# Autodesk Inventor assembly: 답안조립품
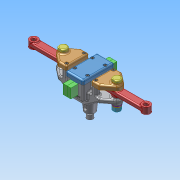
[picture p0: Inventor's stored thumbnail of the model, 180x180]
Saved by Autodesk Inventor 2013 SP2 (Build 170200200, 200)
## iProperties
Created: 2025-07
Part Number: 답안조립품
Document SubType Name: Assembly
Designer: a
Author: a
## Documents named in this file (11)
- C:\Users\a\Desktop\750703V1007\답안조립품.iam
- C:\Users\a\Desktop\750703V1007\본체.ipt
- C:\Users\a\Desktop\750703V1007\링크.ipt
- C:\Users\a\Desktop\750703V1007\슬라이더.ipt
- C:\Users\a\Desktop\750703V1007\링크 커버.ipt
- C:\Users\a\Desktop\750703V1007\슬라이더 커버.ipt
- C:\Users\a\Desktop\750703V1007\평 와셔 M8.ipt
- C:\Users\a\Desktop\750703V1007\스프링 와셔 M8.ipt
- C:\Users\a\Desktop\750703V1007\6각 너트 M8.ipt
- C:\Users\a\Desktop\750703V1007\핀.ipt
- C:\Users\a\Desktop\750703V1007\6각 구멍붙이 볼트 M3x10.ipt
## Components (12 placed, 3 different names)
1. 6각 너트 M8:1 — 각도:5
2. 핀:1 — 각도:4
3. 핀:2 — 각도:2
4. 6각 너트 M8:2 — 각도:3
5. 6각 구멍붙이 볼트 M3x10:1
6. 6각 구멍붙이 볼트 M3x10:2
7. 6각 구멍붙이 볼트 M3x10:3
8. 6각 구멍붙이 볼트 M3x10:4
9. 6각 구멍붙이 볼트 M3x10:5
10. 6각 구멍붙이 볼트 M3x10:6
11. 6각 구멍붙이 볼트 M3x10:7
12. 6각 구멍붙이 볼트 M3x10:8
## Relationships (4: Angle 4)
- 각도:2 [Angle]: 핀:2
- 각도:3 [Angle]: 6각 너트 M8:2
- 각도:4 [Angle]: 핀:1
- 각도:5 [Angle]: 6각 너트 M8:1
